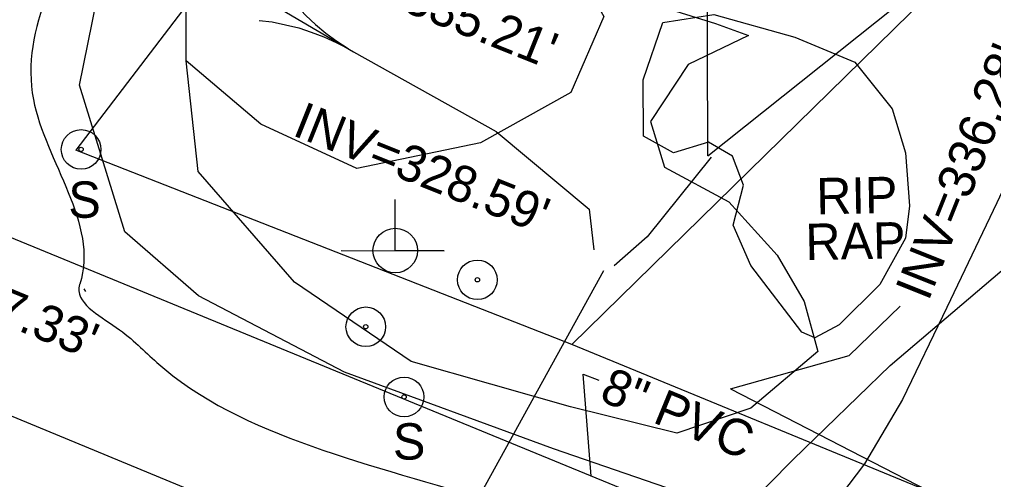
# Model space of a CAD drawing. Extents: x 2089016 to 2094354, y 862840 to 864725.
# Drawn here: x 2091346.4 to 2091453.5, y 863696.1 to 863746.7 of the extents above; entities that cross this region are included whole.
import ezdxf

# ---------------------------------------------------------------- set-up
doc = ezdxf.new("R2010")
doc.units = 0
for name, color, linetype in [('Exist Horizontal Alignment', 7, 'Continuous'), ('Exist Hydro Jurisdictional Stream or Body of Water', 7, 'Continuous'), ('Exist Hydro Stream Flow Arrow CELL', 7, 'Continuous'), ('Exist Other Culture Area Outline', 7, 'Continuous'), ('Exist Other Culture Area Outline Text', 7, 'Continuous'), ('Exist Other Culture Sign Text', 7, 'Continuous'), ('Exist Property Line', 7, 'Continuous'), ('Exist Right of Way Line', 7, 'Continuous'), ('Exist Roads EOP', 7, 'Continuous'), ('Exist Roads Soil', 7, 'Continuous'), ('Exist Structure Minor Pipes CMP 54 Inch', 7, 'Continuous'), ('Exist Structure Minor Pipes CMP 54 Inch Invert', 7, 'Continuous'), ('Exist Structure Minor Pipes HDPE 36 Inch', 7, 'Continuous'), ('Exist Structure Minor Pipes HDPE 36 Inch Invert', 7, 'Continuous'), ('Exist Structure Minor Pipes HDPE 36 Inch Leader', 7, 'Continuous'), ('Exist Structure Minor Pipes RCP 18 Inch', 7, 'Continuous'), ('Exist Structure Minor Pipes RCP 18 Inch Invert', 7, 'Continuous'), ('Exist Structure Minor Pipes RCP 18 Inch Leader', 7, 'Continuous'), ('Exist Utilities Gas UG Line SUE LOS B', 7, 'Continuous'), ('Exist Utilities Sanitary Sewer UG Line', 7, 'Continuous'), ('Exist Utilities Sanitary Sewer UG Line Invert Elevation', 7, 'Continuous'), ('Exist Utilities Sanitary Sewer UG Line Leader', 7, 'Continuous'), ('Exist Utilities Sanitary Sewer UG Line Text', 7, 'Continuous'), ('Exist Vegetation Hedge Row', 7, 'Continuous'), ('Exist Vegetation Woods Line', 7, 'Continuous'), ('Prop Conc Driveway', 7, 'Continuous'), ('Prop Drainage Structure Pipe RCP 36in Class IV', 7, 'Continuous'), ('Prop SS Fill Line', 7, 'Continuous')]:
    doc.layers.add(name, color=color, linetype=linetype)

msp = doc.modelspace()

# ---------------------------------------------------------------- linework, layer by layer
at = {"layer": 'Exist Horizontal Alignment'}
msp.add_line((2091094.5826113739, 863807.0980652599), (2091447.5710816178, 863660.7928895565), dxfattribs=at)
msp.add_arc((2091607.228981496, 863570.6628995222), 325, 141.57592603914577, 153.58273838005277, dxfattribs=at)
at = {"layer": 'Exist Hydro Jurisdictional Stream or Body of Water'}
for points in [[(2091365.4267000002, 863753.1838), (2091373.4542, 863748.8453), (2091383.1367, 863743.1598000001), (2091398.8094, 863734.3958), (2091409.0506, 863725.8441), (2091409.5491, 863721.353)], [(2091422.4626261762, 863731.5487424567), (2091415.436, 863722.7856), (2091411.8127, 863719.6020000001)]]:
    msp.add_lwpolyline(points, dxfattribs=at)
at = {"layer": 'Exist Hydro Stream Flow Arrow CELL'}
msp.add_line((2091378.22848462, 863746.0418716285), (2091378.22848462, 863746.0418716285), dxfattribs=at)
for points in [[(2091375.0751329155, 863750.5462061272), (2091375.9246832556, 863749.3515637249), (2091376.9193106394, 863748.231185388), (2091377.915817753, 863747.1386946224), (2091378.975618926, 863746.1539946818), (2091380.1165128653, 863745.2086516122), (2091381.3169414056, 863744.3153242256), (2091382.5401176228, 863743.5101092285)], [(2091372.7585703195, 863746.6010619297), (2091374.2157436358, 863746.441211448), (2091375.6787470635, 863746.1184852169), (2091377.1183125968, 863745.7805302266), (2091378.49458407, 863745.3347844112), (2091379.8759954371, 863744.7990464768), (2091381.2409885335, 863744.1859752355), (2091382.5401176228, 863743.5101092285)]]:
    msp.add_lwpolyline(points, dxfattribs=at)
at = {"layer": 'Exist Other Culture Area Outline'}
msp.add_lwpolyline([(2091432.441782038, 863712.31156035), (2091426.8357351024, 863719.6635224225), (2091424.8893797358, 863724.0703385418), (2091426.0011031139, 863728.4920100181), (2091424.8170505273, 863731.678633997), (2091422.1717969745, 863733.2148118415), (2091418.3095100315, 863732.0315582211), (2091415.0409726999, 863733.8943755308), (2091415.0000531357, 863740.0775910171), (2091417.1391861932, 863746.394284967), (2091422.76146799, 863747.2754663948), (2091431.6479845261, 863744.752490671), (2091438.265070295, 863742.0121652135), (2091442.3756741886, 863736.8848809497), (2091443.8444120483, 863732.0363395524), (2091444.2735709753, 863726.2109780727), (2091443.8454782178, 863722.6687169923), (2091441.0094385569, 863717.5521270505), (2091436.5411990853, 863713.1277543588), (2091433.848728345, 863711.6885355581), (2091432.441782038, 863712.31156035)], dxfattribs=at)
at = {"layer": 'Exist Property Line'}
msp.add_line((2091407.1543656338, 863710.9601327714), (2091503.717, 863805.6478), dxfattribs=at)
at = {"layer": 'Exist Right of Way Line'}
for p, q in [((2091413.5660667, 863812.5106902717), (2091352.6280128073, 863732.3412000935)), ((2091407.1543656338, 863710.9601327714), (2091352.6280128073, 863732.3412000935)), ((2091575.8331911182, 863641.4930312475), (2091407.1543656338, 863710.9601327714))]:
    msp.add_line(p, q, dxfattribs=at)
at = {"layer": 'Exist Roads EOP'}
msp.add_lwpolyline([(2091353.490318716, 863717.0939158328), (2091353.6874311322, 863716.7932984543)], dxfattribs=at)
for points in [[(2090159.8571, 864177.4522), (2090180.6725, 864168.7302000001), (2090222.8594, 864151.6485), (2090264.3934, 864134.6019), (2090306.0047000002, 864117.7894), (2090347.2409, 864101.0471000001), (2090392.9939, 864082.5727), (2090433.2011, 864065.09), (2090472.8293000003, 864048.9636), (2090514.7308, 864032.4301), (2090559.9738, 864014.0483000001), (2090601.369, 863997.1904), (2090646.2914000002, 863978.8154), (2090688.9540000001, 863961.2748000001), (2090733.3817, 863942.9564), (2090770.0545, 863927.3349), (2090814.5164, 863908.7231), (2090858.9124, 863890.9963), (2090901.1465, 863874.1742), (2090939.8657000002, 863858.2796), (2090962.7205, 863848.636), (2090997.5425, 863834.7175), (2091036.0659, 863819.0768), (2091075.6024, 863802.4824), (2091112.8771, 863787.7685), (2091153.6392, 863770.6456), (2091194.6668, 863753.4881), (2091234.0738, 863737.2293), (2091276.5693000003, 863719.3300000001), (2091296.5569, 863710.7485), (2091332.881, 863695.6705), (2091370.7143000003, 863680.0496), (2091411.4527, 863662.8458), (2091427.0088, 863655.9048000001), (2091440.1865, 863646.8024000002), (2091448.8258, 863640.6190000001), (2091463.6724, 863633.8477), (2091467.987, 863632.1682), (2091469.1099, 863631.0712000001), (2091469.9741, 863630.0355), (2091470.3678, 863629.277)], [(2091458.6303000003, 863915.3002), (2091455.432, 863907.1622), (2091438.1719, 863872.8925000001), (2091417.8171, 863841.3111), (2091394.128, 863810.135), (2091368.8269000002, 863778.3267), (2091355.5953, 863760.4843), (2091347.9526, 863737.9204), (2091353.0504, 863717.6041), (2091353.0352, 863717.5561), (2091357.066, 863712.8221), (2091361.5023, 863708.9890000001), (2091398.612, 863693.5742), (2091435.1692, 863678.9551), (2091472.8795, 863664.1351), (2091513.0668, 863651.4162), (2091550.2818, 863640.4362000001), (2091559.5856, 863639.1286), (2091561.1682000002, 863638.354), (2091573.0702000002, 863633.8493), (2091588.6146, 863630.0184), (2091610.9193, 863627.5724), (2091621.3267, 863629.0367)]]:
    msp.add_spline(points, degree=3, dxfattribs=at)
at = {"layer": 'Exist Roads Soil'}
msp.add_lwpolyline([(2091553.918080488, 863822.1500853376), (2091537.8342624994, 863815.0600355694), (2091525.3835390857, 863808.5703749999), (2091513.9705353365, 863801.8890917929), (2091505.696773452, 863796.1664997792), (2091495.7988818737, 863788.3125949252), (2091488.7412224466, 863779.5385616), (2091480.2909264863, 863769.205751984), (2091470.6873331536, 863756.644678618), (2091464.1538230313, 863746.0329819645), (2091458.430269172, 863736.221390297), (2091453.8710488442, 863726.5527566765), (2091448.3828606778, 863715.0239940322), (2091443.4809514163, 863704.9123354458), (2091439.3125635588, 863697.8094776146), (2091436.668197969, 863694.322845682), (2091433.7832561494, 863691.7603609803), (2091429.5870341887, 863690.3873480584), (2091423.0276464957, 863688.4608977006), (2091417.1969191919, 863686.8474960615)], dxfattribs=at)
at = {"layer": 'Exist Structure Minor Pipes CMP 54 Inch'}
msp.add_line((2091410.636804, 863719.0438910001), (2091377.2859595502, 863658.5466436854), dxfattribs=at)
at = {"layer": 'Exist Structure Minor Pipes HDPE 36 Inch'}
msp.add_lwpolyline([(2091422.1142999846, 863731.7260999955), (2091576.9103426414, 863855.1811126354), (2091581.4254530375, 863856.5031449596), (2091588.4146239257, 863859.0712077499), (2091593.3257440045, 863861.3372631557), (2091597.9798577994, 863863.313311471), (2091603.293987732, 863866.3783864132), (2091607.4530894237, 863870.3144826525), (2091614.0492507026, 863875.5496106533), (2091619.4933838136, 863880.1697236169), (2091630.2476467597, 863889.6919564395), (2091672.7946, 863927.5499999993)], dxfattribs=at)
at = {"layer": 'Exist Structure Minor Pipes HDPE 36 Inch Leader'}
msp.add_lwpolyline([(2091422.1142999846, 863731.7260999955), (2091422.0177175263, 863756.0046513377), (2091414.7577096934, 863759.9686797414)], dxfattribs=at)
at = {"layer": 'Exist Structure Minor Pipes RCP 18 Inch'}
msp.add_line((2091424.5799000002, 863706.0796), (2091521.0989, 863656.4111), dxfattribs=at)
at = {"layer": 'Exist Structure Minor Pipes RCP 18 Inch Leader'}
msp.add_lwpolyline([(2091424.5799000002, 863706.0795999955), (2091437.6271169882, 863709.7379652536), (2091443.239147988, 863715.1722548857)], dxfattribs=at)
at = {"layer": 'Exist Utilities Gas UG Line SUE LOS B'}
for points in [[(2091490.4776, 863668.0603), (2091475.9759, 863673.4851), (2091454.7935000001, 863681.9523), (2091442.977, 863687.3758), (2091425.4537000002, 863692.4735), (2091405.1451, 863699.4609), (2091382.1647, 863707.9082), (2091366.1108, 863716.317), (2091358.0052, 863723.3572), (2091353.0253000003, 863739.4785), (2091355.8224, 863753.4128), (2091363.5069, 863765.6465), (2091372.7623, 863777.9747), (2091383.6628, 863793.1623), (2091402.9612, 863818.4864000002), (2091414.6806, 863834.229), (2091432.9613000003, 863863.0215), (2091438.2912, 863868.6516000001), (2091446.7832000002, 863880.5545)], [(2091425.5053000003, 863692.4056), (2091426.0285, 863692.7499000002), (2091431.4924, 863698.3036), (2091442.1496, 863708.6511), (2091468.9748, 863731.4911), (2091485.6544, 863753.1749), (2091496.7194, 863765.1375000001)]]:
    msp.add_lwpolyline(points, dxfattribs=at)
at = {"layer": 'Exist Utilities Sanitary Sewer UG Line'}
msp.add_lwpolyline([(2091320.5947000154, 863732.9499999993), (2091428.4911, 863688.5947999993), (2091601.0812999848, 863620.3436999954), (2091645.503099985, 863589.9982999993), (2091742.609, 863559.5980999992), (2091989.8538772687, 863486.5238441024)], dxfattribs=at)
at = {"layer": 'Exist Utilities Sanitary Sewer UG Line Leader'}
msp.add_lwpolyline([(2091409.2565889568, 863696.461531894), (2091408.4031376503, 863707.6938333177), (2091410.115902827, 863707.0165172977)], dxfattribs=at)
at = {"layer": 'Exist Vegetation Hedge Row'}
for points in [[(2091407.460308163, 863752.7038558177), (2091414.3382970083, 863748.9973080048), (2091422.955080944, 863746.2790752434), (2091426.5852490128, 863744.9578123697), (2091419.9261826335, 863741.7620312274), (2091415.8097524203, 863735.4857081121), (2091417.331253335, 863730.4748343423), (2091424.4088061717, 863726.6435506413), (2091429.724087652, 863720.7924211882), (2091432.6962298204, 863715.6769064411), (2091434.1789514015, 863710.1783970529)], [(2091434.1789514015, 863710.1783970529), (2091426.8291732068, 863703.9596199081), (2091418.670825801, 863701.2005938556), (2091406.9906094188, 863704.0906945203), (2091389.4891956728, 863709.0940294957), (2091376.653774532, 863717.826076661), (2091366.0742565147, 863730.0042741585), (2091364.7622691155, 863742.1506207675)]]:
    msp.add_lwpolyline(points, dxfattribs=at)
at = {"layer": 'Exist Vegetation Woods Line'}
msp.add_lwpolyline([(2091379.049648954, 863768.3215136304), (2091396.221268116, 863759.5341126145), (2091407.460308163, 863752.7038558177), (2091410.6706628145, 863747.0473375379), (2091407.030575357, 863738.6820078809), (2091397.0941486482, 863733.1547056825), (2091383.492919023, 863730.3072912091), (2091372.9619852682, 863735.1835118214), (2091364.7622691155, 863742.1506207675), (2091364.7408980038, 863750.8318709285), (2091367.6469490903, 863759.414749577), (2091379.049648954, 863768.3215136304)], dxfattribs=at)
at = {"layer": 'Prop Conc Driveway'}
for centre, radius in [((2091353.193599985, 863732.4191999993), 2.1799154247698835), ((2091353.193599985, 863732.4191999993), 0.24011715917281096), ((2091388.6945, 863705.178400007), 2.1799154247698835), ((2091388.6945, 863705.178400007), 0.24011715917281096)]:
    msp.add_circle(centre, radius, dxfattribs=at)
at = {"layer": 'Prop Drainage Structure Pipe RCP 36in Class IV'}
for centre, radius in [((2091396.757099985, 863718.0705999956), 2.1799154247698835), ((2091396.757099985, 863718.0705999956), 0.24011715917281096), ((2091384.4906, 863712.9044000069), 2.1799154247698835), ((2091384.4906, 863712.9044000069), 0.24011715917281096)]:
    msp.add_circle(centre, radius, dxfattribs=at)
at = {"layer": 'Prop SS Fill Line'}
msp.add_line((2091387.726099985, 863721.2865999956), (2091387.726099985, 863721.2865999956), dxfattribs=at)
msp.add_lwpolyline([(2091381.788599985, 863721.2865999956), (2091393.1260999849, 863721.2490999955), (2091387.726099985, 863721.2669610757), (2091387.726099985, 863726.9115999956)], dxfattribs=at)
msp.add_circle((2091387.7273114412, 863721.2928499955), 2.450127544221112, dxfattribs=at)

# ---------------------------------------------------------------- texts
at = {"layer": 'Exist Other Culture Area Outline Text'}
for s, p in [('RIP ', (2091434.0583580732, 863725.2699894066)), ('RAP', (2091432.863598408, 863720.2381997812))]:
    msp.add_text(s, height=4.000000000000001, rotation=1.1023065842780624, dxfattribs=at).set_placement(p)
at = {"layer": 'Exist Other Culture Sign Text'}
for p in [(2091351.7896485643, 863724.8973037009), (2091387.4749434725, 863698.2876155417)]:
    msp.add_text('S', height=4, dxfattribs=at).set_placement(p)
at = {"layer": 'Exist Structure Minor Pipes CMP 54 Inch Invert'}
msp.add_text("INV=328.59'", height=4.0000000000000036, rotation=338.1908714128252, dxfattribs=at).set_placement((2091376.2871891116, 863734.023067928))
at = {"layer": 'Exist Structure Minor Pipes HDPE 36 Inch Invert'}
msp.add_text("INV=335.21'", height=4.000000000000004, rotation=338.1164486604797, dxfattribs=at).set_placement((2091377.1686866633, 863752.2298124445))
at = {"layer": 'Exist Structure Minor Pipes RCP 18 Inch Invert'}
msp.add_text("INV=336.28'", height=4.000000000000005, rotation=68.24583814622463, dxfattribs=at).set_placement((2091446.3390359, 863715.6139103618))
at = {"layer": 'Exist Utilities Sanitary Sewer UG Line Invert Elevation'}
msp.add_text("INV=337.33'", height=3.999999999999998, rotation=337.6528950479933, dxfattribs=at).set_placement((2091326.7626229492, 863720.4912490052))
at = {"layer": 'Exist Utilities Sanitary Sewer UG Line Text'}
msp.add_text('8" PVC', height=3.9999999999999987, rotation=337.6528950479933, dxfattribs=at).set_placement((2091410.0184012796, 863704.8487228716))

doc.saveas('drawing.dxf')
